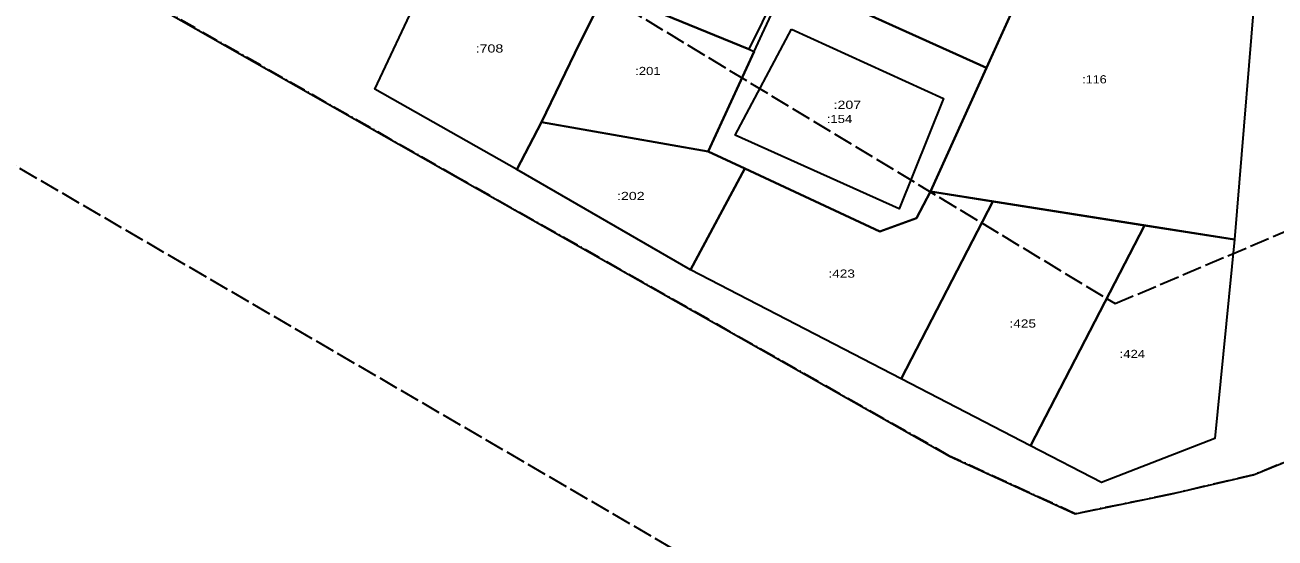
# Model space of a CAD drawing. Extents: x 1185507 to 1197690, y 352608 to 375774.
# Drawn here: x 1190677.6 to 1190907.1, y 364221.4 to 364315.6 of the extents above; entities that cross this region are included whole.
import ezdxf
from ezdxf.enums import TextEntityAlignment as Align

# ---------------------------------------------------------------- set-up
doc = ezdxf.new("R2010")
doc.units = 0
doc.header["$LTSCALE"] = 0.6
doc.linetypes.add('DOT_DASHED', pattern=[7.7, 5, -1.2, 0.3, -1.2])
doc.linetypes.add('LONG_DASHED', pattern=[7.5, 6, -1.5])
for name, color, linetype, lineweight in [('2', 7, 'Continuous', 35), ('4', 7, 'Continuous', 35), ('5', 7, 'DOT_DASHED', 35), ('7', 7, 'LONG_DASHED', 35)]:
    doc.layers.add(name, color=color, linetype=linetype, lineweight=lineweight)

msp = doc.modelspace()

# ---------------------------------------------------------------- linework, layer by layer
at = {"layer": '2'}
for points in [[(1190800.59, 364356.46), (1190827.72, 364346.08), (1190810.56, 364311.15), (1190784.3, 364321.94)], [(1190830.12, 364351.57), (1190866.56, 364335.08), (1190854.19, 364307.74), (1190817.75, 364324.23)], [(1190866.56, 364335.07), (1190904.08, 364329.02), (1190899.68, 364276.2), (1190843.91, 364285.02), (1190854.19, 364307.74)], [(1190755.93, 364333.55), (1190783.97, 364321.28), (1190779.44, 364312.21), (1190772.48, 364297.77), (1190767.95, 364289.05), (1190741.88, 364303.85), (1190749.79, 364320.65)], [(1190841.33, 364280.15), (1190834.58, 364277.69), (1190809.79, 364289.26), (1190803.07, 364292.4), (1190811.54, 364310.75), (1190813.01, 364313.94), (1190817.75, 364324.23), (1190854.19, 364307.74), (1190843.91, 364285.02)], [(1190784.3, 364321.94), (1190810.56, 364311.15), (1190811.54, 364310.75), (1190803.07, 364292.4), (1190772.48, 364297.77), (1190779.44, 364312.21)], [(1190818.37, 364314.86), (1190846.31, 364302.13), (1190838.16, 364281.85), (1190808.06, 364295.39)], [(1190809.79, 364289.26), (1190799.84, 364270.66), (1190767.95, 364289.05), (1190772.48, 364297.77), (1190803.07, 364292.4)], [(1190799.84, 364270.66), (1190809.79, 364289.26), (1190834.58, 364277.69), (1190841.33, 364280.15), (1190843.91, 364285.02), (1190855.33, 364283.21), (1190838.48, 364250.66)], [(1190855.33, 364283.21), (1190883.18, 364278.8), (1190862.24, 364238.36), (1190838.48, 364250.66)], [(1190883.18, 364278.8), (1190899.68, 364276.2), (1190896.1, 364239.67), (1190875.27, 364231.61), (1190862.24, 364238.36)]]:
    msp.add_lwpolyline(points, close=True, dxfattribs=at)
at = {"layer": '4'}
msp.add_lwpolyline([(1190647.14, 364349.43), (1190692.88, 364324.17), (1190757.05, 364287.63), (1190847.4, 364236.46), (1190870.47, 364225.86), (1190887.93, 364229.43), (1190903.2, 364233), (1190963.17, 364257.43), (1190977.58, 364249.06), (1191018.45, 364240.46), (1191053.56, 364275.17), (1191077.75, 364294.16)], dxfattribs=at)
at = {"layer": '5'}
msp.add_lwpolyline([(1190977.58, 364249.06), (1190963.17, 364257.43), (1190903.2, 364233), (1190887.93, 364229.43), (1190870.47, 364225.86), (1190847.4, 364236.46), (1190757.05, 364287.63), (1190692.88, 364324.17), (1190647.14, 364349.43), (1190632.21, 364356.82), (1190626.4, 364363.08), (1190622.19, 364369.01), (1190611.28, 364369.51), (1190595.22, 364367.23), (1190532.29, 364357.36), (1190463.09, 364355.18), (1190404.66, 364360.8), (1190352.99, 364368.35)], dxfattribs=at)
at = {"layer": '7'}
for points in [[(1192415.6, 364440.24), (1191866.38, 364672.34), (1191840.46, 364707.47), (1191734.83, 364812.28), (1191719.9, 364840.01), (1191472.73, 364953.87), (1191341.42, 364915.36), (1191218, 364742.83), (1191294.12, 364597.33), (1191343, 364505.77), (1191359.36, 364477.47), (1191352.83, 364440.49), (1191325.5, 364415.55), (1191208.53, 364347.34), (1191030.05, 364198.94), (1190997.05, 364201.53), (1190961.38, 364212.57), (1190883.65, 364181.63), (1190850.92, 364187.77), (1190612.74, 364326.54)], [(1189181.53, 364482.48), (1189344.66, 364521.04), (1189504.15, 364533.94), (1189608.74, 364531.21), (1189675.93, 364518.82), (1189812.58, 364539.7), (1189922.37, 364516.11), (1190113.06, 364450.97), (1190189.38, 364420.33), (1190281.14, 364404.98), (1190362.32, 364410.03), (1190480.68, 364396.9), (1190633.76, 364412.12), (1190877.81, 364264.44), (1190958.03, 364298.57), (1191010.79, 364286.96), (1191124.41, 364386.71)]]:
    msp.add_lwpolyline(points, dxfattribs=at)

# ---------------------------------------------------------------- texts
at = {"layer": '2'}
for s, width, p in [(':708', 1.3, (1190762.9255, 364310.55)), (':201', 1.2, (1190792.01, 364306.42)), (':116', 1.15, (1190873.9945, 364304.885)), (':207', 1.3, (1190828.6305, 364300.21)), (':154', 1.2, (1190827.185, 364297.605)), (':202', 1.3, (1190788.8705, 364283.465)), (':423', 1.25, (1190827.5855, 364269.21)), (':425', 1.25, (1190860.8305, 364260.035)), (':424', 1.2, (1190880.96, 364254.455))]:
    msp.add_text(s, height=1.5, dxfattribs=dict(at, width=width)).set_placement(p, align=Align.CENTER)

doc.saveas('drawing.dxf')
